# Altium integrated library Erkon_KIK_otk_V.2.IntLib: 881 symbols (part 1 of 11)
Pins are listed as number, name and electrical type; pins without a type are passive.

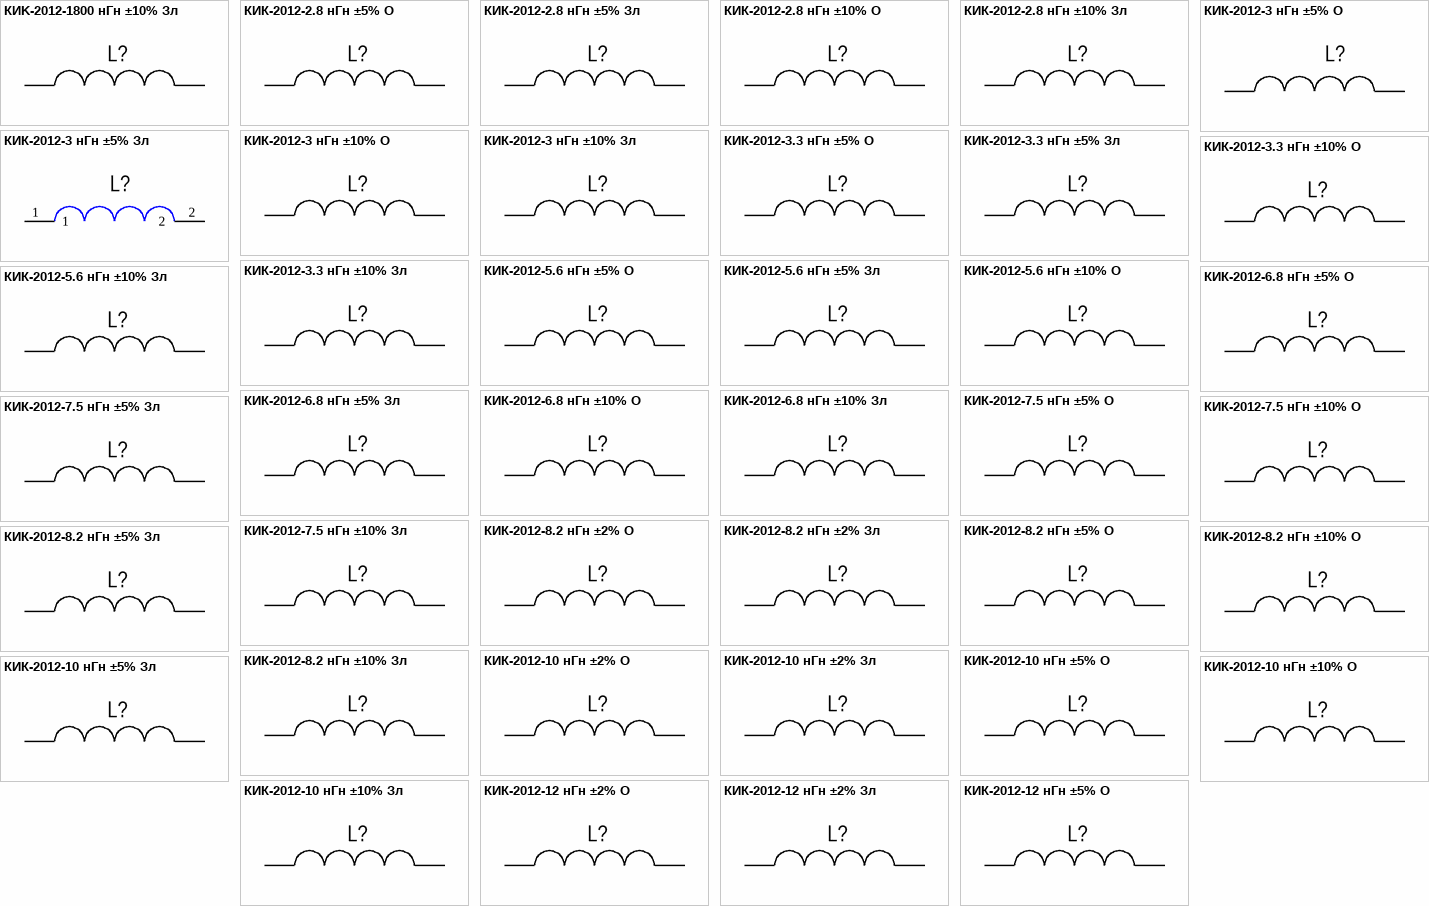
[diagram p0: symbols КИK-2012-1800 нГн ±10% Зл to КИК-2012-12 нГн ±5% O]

## КИK-2012-1800 нГн ±10% Зл
designator L?, comment 1800 нГн ±10%  (value not drawn)
Катушка индуктивности с керамическим сердечником и золотым покрытием контактных площадок; Добротность, не менее: 17; Резонансная частота, не менее: 0.120 ГГц; Сопротивление обмотки постоянноми току, не более: 3 Ом; Допустимый ток обмотки: 120 мА; Диапазон рабочих температур: от -60 до +125 ℃; Упаковка: Катушка и лента; Типоразмер: 2012 (0805); Технология монтажа: SMT; Изготовитель: АО "НПО "ЭРКОН"
footprint КИК-2012-Зл (Катушка индуктивности с керамическим сердечникомтипоразмер 2012(0805))
pins: 1, 2

## КИК-2012-2.8 нГн ±5% O
designator L?, comment 2.8 нГн ±5%  (value not drawn)
Катушка индуктивности с керамическим сердечником и  финишным покрытием контактных площадок оловом; Номиналиная индуктивность: 2.8 нГн; Добротность, не менее: 30; Резонансная частота, не менее: 12.20 ГГц; Сопротивление обмотки постоянноми току, не более: 0.06 Ом; Допустимый ток обмотки: 800 мА; Диапазон рабочих температур: от -60 до +125 ℃; Упаковка: Катушка и лента; Технология монтажа: SMT; Изготовитель: АО "НПО "ЭРКОН"; Типоразмер: 2012 (0805)
footprint КИК-2012-O (Катушка индуктивности с керамическим сердечником типоразмер 2012(0805))
pins: 1, 2

## КИК-2012-2.8 нГн ±5% Зл
designator L?, comment 2.8 нГн ±5%  (value not drawn)
Катушка индуктивности с керамическим сердечником и золотым покрытием контактных площадок; Номиналиная индуктивность: 2.8 нГн; Добротность, не менее: 30; Резонансная частота, не менее: 12.20 ГГц; Сопротивление обмотки постоянноми току, не более: 0.06 Ом; Допустимый ток обмотки: 800 мА; Диапазон рабочих температур: от -60 до +125 ℃; Упаковка: Катушка и лента; Типоразмер: 2012 (0805); Технология монтажа: SMT; Изготовитель: АО "НПО "ЭРКОН"
footprint КИК-2012-Зл (Катушка индуктивности с керамическим сердечникомтипоразмер 2012(0805))
pins: 1, 2

## КИК-2012-2.8 нГн ±10% O
designator L?, comment 2.8 нГн ±10%  (value not drawn)
Катушка индуктивности с керамическим сердечником и  финишным покрытием контактных площадок оловом; Номиналиная индуктивность: 2.8 нГн; Добротность, не менее: 30; Резонансная частота, не менее: 12.20 ГГц; Сопротивление обмотки постоянноми току, не более: 0.06 Ом; Допустимый ток обмотки: 800 мА; Диапазон рабочих температур: от -60 до +125 ℃; Упаковка: Катушка и лента; Типоразмер: 2012 (0805); Технология монтажа: SMT; Изготовитель: АО "НПО "ЭРКОН"
footprint КИК-2012-O (Катушка индуктивности с керамическим сердечником типоразмер 2012(0805))
pins: 1, 2

## КИК-2012-2.8 нГн ±10% Зл
designator L?, comment 2.8 нГн ±10%  (value not drawn)
Катушка индуктивности с керамическим сердечником и золотым покрытием контактных площадок; Номиналиная индуктивность: 2.8 нГн; Добротность, не менее: 30; Резонансная частота, не менее: 12.20 ГГц; Сопротивление обмотки постоянноми току, не более: 0.06 Ом; Допустимый ток обмотки: 800 мА; Диапазон рабочих температур: от -60 до +125 ℃; Упаковка: Катушка и лента; Типоразмер: 2012 (0805); Технология монтажа: SMT; Изготовитель: АО "НПО "ЭРКОН"
footprint КИК-2012-Зл (Катушка индуктивности с керамическим сердечникомтипоразмер 2012(0805))
pins: 1, 2

## КИК-2012-3 нГн ±5% O
designator L?, comment 3 нГн ±5%  (value not drawn)
Катушка индуктивности с керамическим сердечником и  финишным покрытием контактных площадок оловом; Номиналиная индуктивность: 3 нГн; Добротность, не менее: 30; Резонансная частота, не менее: 12.20 ГГц; Сопротивление обмотки постоянноми току, не более: 0.06 Ом; Допустимый ток обмотки: 800 мА; Диапазон рабочих температур: от -60 до +125 ℃; Упаковка: Катушка и лента; Типоразмер: 2012 (0805); Технология монтажа: SMT; Изготовитель: АО "НПО "ЭРКОН"
footprint КИК-2012-O (Катушка индуктивности с керамическим сердечником типоразмер 2012(0805))
pins: 1, 2

## КИК-2012-3 нГн ±5% Зл
designator L?, comment 3 нГн ±5%  (value not drawn)
Катушка индуктивности с керамическим сердечником и золотым покрытием контактных площадок; Номиналиная индуктивность: 3 нГн; Добротность, не менее: 30; Резонансная частота, не менее: 12.20 ГГц; Сопротивление обмотки постоянноми току, не более: 0.06 Ом; Допустимый ток обмотки: 800 мА; Диапазон рабочих температур: от -60 до +125 ℃; Упаковка: Катушка и лента; Типоразмер: 2012 (0805); Технология монтажа: SMT; Изготовитель: АО "НПО "ЭРКОН"
footprint КИК-2012-Зл (Катушка индуктивности с керамическим сердечникомтипоразмер 2012(0805))
pins: 1, 2

## КИК-2012-3 нГн ±10% O
designator L?, comment 3 нГн ±10%  (value not drawn)
Катушка индуктивности с керамическим сердечником и  финишным покрытием контактных площадок оловом; Номиналиная индуктивность: 3 нГн; Добротность, не менее: 30; Резонансная частота, не менее: 12.20 ГГц; Сопротивление обмотки постоянноми току, не более: 0.06 Ом; Допустимый ток обмотки: 800 мА; Диапазон рабочих температур: от -60 до +125 ℃; Упаковка: Катушка и лента; Типоразмер: 2012 (0805); Технология монтажа: SMT; Изготовитель: АО "НПО "ЭРКОН"
footprint КИК-2012-O (Катушка индуктивности с керамическим сердечником типоразмер 2012(0805))
pins: 1, 2

## КИК-2012-3 нГн ±10% Зл
designator L?, comment 3 нГн ±10%  (value not drawn)
Катушка индуктивности с керамическим сердечником и золотым покрытием контактных площадок; Номиналиная индуктивность: 3 нГн; Добротность, не менее: 30; Резонансная частота, не менее: 12.20 ГГц; Сопротивление обмотки постоянноми току, не более: 0.06 Ом; Допустимый ток обмотки: 800 мА; Диапазон рабочих температур: от -60 до +125 ℃; Упаковка: Катушка и лента; Типоразмер: 2012 (0805); Технология монтажа: SMT; Изготовитель: АО "НПО "ЭРКОН"
footprint КИК-2012-Зл (Катушка индуктивности с керамическим сердечникомтипоразмер 2012(0805))
pins: 1, 2

## КИК-2012-3.3 нГн ±5% O
designator L?, comment 3.3 нГн ±5%  (value not drawn)
Катушка индуктивности с керамическим сердечником и  финишным покрытием контактных площадок оловом; Номиналиная индуктивность: 3.3 нГн; Добротность, не менее: 30; Резонансная частота, не менее: 12.20 ГГц; Сопротивление обмотки постоянноми току, не более: 0.08 Ом; Допустимый ток обмотки: 600 мА; Диапазон рабочих температур: от -60 до +125 ℃; Упаковка: Катушка и лента; Типоразмер: 2012 (0805); Технология монтажа: SMT; Изготовитель: АО "НПО "ЭРКОН"
footprint КИК-2012-O (Катушка индуктивности с керамическим сердечником типоразмер 2012(0805))
pins: 1, 2

## КИК-2012-3.3 нГн ±5% Зл
designator L?, comment 3.3 нГн ±5%  (value not drawn)
Катушка индуктивности с керамическим сердечником и золотым покрытием контактных площадок; Номиналиная индуктивность: 3.3 нГн; Добротность, не менее: 30; Резонансная частота, не менее: 12.20 ГГц; Сопротивление обмотки постоянноми току, не более: 0.08 Ом; Допустимый ток обмотки: 600 мА; Диапазон рабочих температур: от -60 до +125 ℃; Упаковка: Катушка и лента; Типоразмер: 2012 (0805); Технология монтажа: SMT; Изготовитель: АО "НПО "ЭРКОН"
footprint КИК-2012-Зл (Катушка индуктивности с керамическим сердечникомтипоразмер 2012(0805))
pins: 1, 2

## КИК-2012-3.3 нГн ±10% O
designator L?, comment 3.3 нГн ±10%  (value not drawn)
Катушка индуктивности с керамическим сердечником и  финишным покрытием контактных площадок оловом; Номиналиная индуктивность: 3.3 нГн; Добротность, не менее: 30; Резонансная частота, не менее: 12.20 ГГц; Сопротивление обмотки постоянноми току, не более: 0.08 Ом; Допустимый ток обмотки: 600 мА; Диапазон рабочих температур: от -60 до +125 ℃; Упаковка: Катушка и лента; Типоразмер: 2012 (0805); Технология монтажа: SMT; Изготовитель: АО "НПО "ЭРКОН"
footprint КИК-2012-O (Катушка индуктивности с керамическим сердечником типоразмер 2012(0805))
pins: 1, 2

## КИК-2012-3.3 нГн ±10% Зл
designator L?, comment 3.3 нГн ±10%  (value not drawn)
Катушка индуктивности с керамическим сердечником и золотым покрытием контактных площадок; Номиналиная индуктивность: 3.3 нГн; Добротность, не менее: 30; Резонансная частота, не менее: 12.20 ГГц; Сопротивление обмотки постоянноми току, не более: 0.08 Ом; Допустимый ток обмотки: 600 мА; Диапазон рабочих температур: от -60 до +125 ℃; Упаковка: Катушка и лента; Типоразмер: 2012 (0805); Технология монтажа: SMT; Изготовитель: АО "НПО "ЭРКОН"
footprint КИК-2012-Зл (Катушка индуктивности с керамическим сердечникомтипоразмер 2012(0805))
pins: 1, 2

## КИК-2012-5.6 нГн ±5% O
designator L?, comment 5.6 нГн ±5%  (value not drawn)
Катушка индуктивности с керамическим сердечником и  финишным покрытием контактных площадок оловом; Номиналиная индуктивность: 5.6 нГн; Добротность, не менее: 50; Резонансная частота, не менее: 5.90 ГГц; Сопротивление обмотки постоянноми току, не более: 0.08 Ом; Допустимый ток обмотки: 600 мА; Диапазон рабочих температур: от -60 до +125 ℃; Упаковка: Катушка и лента; Типоразмер: 2012 (0805); Технология монтажа: SMT; Изготовитель: АО "НПО "ЭРКОН"
footprint КИК-2012-O (Катушка индуктивности с керамическим сердечником типоразмер 2012(0805))
pins: 1, 2

## КИК-2012-5.6 нГн ±5% Зл
designator L?, comment 5.6 нГн ±5%  (value not drawn)
Катушка индуктивности с керамическим сердечником и золотым покрытием контактных площадок; Номиналиная индуктивность: 5.6 нГн; Добротность, не менее: 50; Резонансная частота, не менее: 5.90 ГГц; Сопротивление обмотки постоянноми току, не более: 0.08 Ом; Допустимый ток обмотки: 600 мА; Диапазон рабочих температур: от -60 до +125 ℃; Упаковка: Катушка и лента; Типоразмер: 2012 (0805); Технология монтажа: SMT; Изготовитель: АО "НПО "ЭРКОН"
footprint КИК-2012-Зл (Катушка индуктивности с керамическим сердечникомтипоразмер 2012(0805))
pins: 1, 2

## КИК-2012-5.6 нГн ±10% O
designator L?, comment 5.6 нГн ±10%  (value not drawn)
Катушка индуктивности с керамическим сердечником и  финишным покрытием контактных площадок оловом; Номиналиная индуктивность: 5.6 нГн; Добротность, не менее: 50; Резонансная частота, не менее: 5.90 ГГц; Сопротивление обмотки постоянноми току, не более: 0.08 Ом; Допустимый ток обмотки: 600 мА; Диапазон рабочих температур: от -60 до +125 ℃; Упаковка: Катушка и лента; Типоразмер: 2012 (0805); Технология монтажа: SMT; Изготовитель: АО "НПО "ЭРКОН"
footprint КИК-2012-O (Катушка индуктивности с керамическим сердечником типоразмер 2012(0805))
pins: 1, 2

## КИК-2012-5.6 нГн ±10% Зл
designator L?, comment 5.6 нГн ±10%  (value not drawn)
Катушка индуктивности с керамическим сердечником и золотым покрытием контактных площадок; Номиналиная индуктивность: 5.6 нГн; Добротность, не менее: 50; Резонансная частота, не менее: 5.90 ГГц; Сопротивление обмотки постоянноми току, не более: 0.08 Ом; Допустимый ток обмотки: 600 мА; Диапазон рабочих температур: от -60 до +125 ℃; Упаковка: Катушка и лента; Типоразмер: 2012 (0805); Технология монтажа: SMT; Изготовитель: АО "НПО "ЭРКОН"
footprint КИК-2012-Зл (Катушка индуктивности с керамическим сердечникомтипоразмер 2012(0805))
pins: 1, 2

## КИК-2012-6.8 нГн ±5% O
designator L?, comment 6.8 нГн ±5%  (value not drawn)
Катушка индуктивности с керамическим сердечником и  финишным покрытием контактных площадок оловом; Номиналиная индуктивность: 6.8 нГн; Добротность, не менее: 50; Резонансная частота, не менее: 5.60 ГГц; Сопротивление обмотки постоянноми току, не более: 0.11 Ом; Допустимый ток обмотки: 600 мА; Диапазон рабочих температур: от -60 до +125 ℃; Упаковка: Катушка и лента; Типоразмер: 2012 (0805); Технология монтажа: SMT; Изготовитель: АО "НПО "ЭРКОН"
footprint КИК-2012-O (Катушка индуктивности с керамическим сердечником типоразмер 2012(0805))
pins: 1, 2

## КИК-2012-6.8 нГн ±5% Зл
designator L?, comment 6.8 нГн ±5%  (value not drawn)
Катушка индуктивности с керамическим сердечником и золотым покрытием контактных площадок; Номиналиная индуктивность: 6.8 нГн; Добротность, не менее: 50; Резонансная частота, не менее: 5.60 ГГц; Сопротивление обмотки постоянноми току, не более: 0.11 Ом; Допустимый ток обмотки: 600 мА; Диапазон рабочих температур: от -60 до +125 ℃; Упаковка: Катушка и лента; Типоразмер: 2012 (0805); Технология монтажа: SMT; Изготовитель: АО "НПО "ЭРКОН"
footprint КИК-2012-Зл (Катушка индуктивности с керамическим сердечникомтипоразмер 2012(0805))
pins: 1, 2

## КИК-2012-6.8 нГн ±10% O
designator L?, comment 6.8 нГн ±10%  (value not drawn)
Катушка индуктивности с керамическим сердечником и  финишным покрытием контактных площадок оловом; Номиналиная индуктивность: 6.8 нГн; Добротность, не менее: 50; Резонансная частота, не менее: 5.60 ГГц; Сопротивление обмотки постоянноми току, не более: 0.11 Ом; Допустимый ток обмотки: 600 мА; Диапазон рабочих температур: от -60 до +125 ℃; Упаковка: Катушка и лента; Типоразмер: 2012 (0805); Технология монтажа: SMT; Изготовитель: АО "НПО "ЭРКОН"
footprint КИК-2012-O (Катушка индуктивности с керамическим сердечником типоразмер 2012(0805))
pins: 1, 2

## КИК-2012-6.8 нГн ±10% Зл
designator L?, comment 6.8 нГн ±10%  (value not drawn)
Катушка индуктивности с керамическим сердечником и золотым покрытием контактных площадок; Номиналиная индуктивность: 6.8 нГн; Добротность, не менее: 50; Резонансная частота, не менее: 5.60 ГГц; Сопротивление обмотки постоянноми току, не более: 0.11 Ом; Допустимый ток обмотки: 600 мА; Диапазон рабочих температур: от -60 до +125 ℃; Упаковка: Катушка и лента; Типоразмер: 2012 (0805); Технология монтажа: SMT; Изготовитель: АО "НПО "ЭРКОН"
footprint КИК-2012-Зл (Катушка индуктивности с керамическим сердечникомтипоразмер 2012(0805))
pins: 1, 2

## КИК-2012-7.5 нГн ±5% O
designator L?, comment 7.5 нГн ±5%  (value not drawn)
Катушка индуктивности с керамическим сердечником и  финишным покрытием контактных площадок оловом; Номиналиная индуктивность: 7.5 нГн; Добротность, не менее: 50; Резонансная частота, не менее: 4.80 ГГц; Сопротивление обмотки постоянноми току, не более: 0.14 Ом; Допустимый ток обмотки: 600 мА; Диапазон рабочих температур: от -60 до +125 ℃; Упаковка: Катушка и лента; Типоразмер: 2012 (0805); Технология монтажа: SMT; Изготовитель: АО "НПО "ЭРКОН"
footprint КИК-2012-O (Катушка индуктивности с керамическим сердечником типоразмер 2012(0805))
pins: 1, 2

## КИК-2012-7.5 нГн ±5% Зл
designator L?, comment 7.5 нГн ±5%  (value not drawn)
Катушка индуктивности с керамическим сердечником и золотым покрытием контактных площадок; Номиналиная индуктивность: 7.5 нГн; Добротность, не менее: 50; Резонансная частота, не менее: 4.80 ГГц; Сопротивление обмотки постоянноми току, не более: 0.14 Ом; Допустимый ток обмотки: 600 мА; Диапазон рабочих температур: от -60 до +125 ℃; Упаковка: Катушка и лента; Типоразмер: 2012 (0805); Технология монтажа: SMT; Изготовитель: АО "НПО "ЭРКОН"
footprint КИК-2012-Зл (Катушка индуктивности с керамическим сердечникомтипоразмер 2012(0805))
pins: 1, 2

## КИК-2012-7.5 нГн ±10% O
designator L?, comment 7.5 нГн ±10%  (value not drawn)
Катушка индуктивности с керамическим сердечником и  финишным покрытием контактных площадок оловом; Номиналиная индуктивность: 7.5 нГн; Добротность, не менее: 50; Резонансная частота, не менее: 4.80 ГГц; Сопротивление обмотки постоянноми току, не более: 0.14 Ом; Допустимый ток обмотки: 600 мА; Диапазон рабочих температур: от -60 до +125 ℃; Упаковка: Катушка и лента; Типоразмер: 2012 (0805); Технология монтажа: SMT; Изготовитель: АО "НПО "ЭРКОН"
footprint КИК-2012-O (Катушка индуктивности с керамическим сердечником типоразмер 2012(0805))
pins: 1, 2

## КИК-2012-7.5 нГн ±10% Зл
designator L?, comment 7.5 нГн ±10%  (value not drawn)
Катушка индуктивности с керамическим сердечником и золотым покрытием контактных площадок; Номиналиная индуктивность: 7.5 нГн; Добротность, не менее: 50; Резонансная частота, не менее: 4.80 ГГц; Сопротивление обмотки постоянноми току, не более: 0.14 Ом; Допустимый ток обмотки: 600 мА; Диапазон рабочих температур: от -60 до +125 ℃; Упаковка: Катушка и лента; Типоразмер: 2012 (0805); Технология монтажа: SMT; Изготовитель: АО "НПО "ЭРКОН"
footprint КИК-2012-Зл (Катушка индуктивности с керамическим сердечникомтипоразмер 2012(0805))
pins: 1, 2

## КИК-2012-8.2 нГн ±2% O
designator L?, comment 8.2 нГн ±2%  (value not drawn)
Катушка индуктивности с керамическим сердечником и  финишным покрытием контактных площадок оловом; Номиналиная индуктивность: 8.2 нГн; Добротность, не менее: 50; Резонансная частота, не менее: 4.40 ГГц; Сопротивление обмотки постоянноми току, не более: 0.12 Ом; Допустимый ток обмотки: 600 мА; Диапазон рабочих температур: от -60 до +125 ℃; Упаковка: Катушка и лента; Типоразмер: 2012 (0805); Технология монтажа: SMT; Изготовитель: АО "НПО "ЭРКОН"
footprint КИК-2012-O (Катушка индуктивности с керамическим сердечником типоразмер 2012(0805))
pins: 1, 2

## КИК-2012-8.2 нГн ±2% Зл
designator L?, comment 8.2 нГн ±2%  (value not drawn)
Катушка индуктивности с керамическим сердечником и золотым покрытием контактных площадок; Номиналиная индуктивность: 8.2 нГн; Добротность, не менее: 50; Резонансная частота, не менее: 4.40 ГГц; Сопротивление обмотки постоянноми току, не более: 0.12 Ом; Допустимый ток обмотки: 600 мА; Диапазон рабочих температур: от -60 до +125 ℃; Упаковка: Катушка и лента; Типоразмер: 2012 (0805); Технология монтажа: SMT; Изготовитель: АО "НПО "ЭРКОН"
footprint КИК-2012-Зл (Катушка индуктивности с керамическим сердечникомтипоразмер 2012(0805))
pins: 1, 2

## КИК-2012-8.2 нГн ±5% O
designator L?, comment 8.2 нГн ±5%  (value not drawn)
Катушка индуктивности с керамическим сердечником и  финишным покрытием контактных площадок оловом; Номиналиная индуктивность: 8.2 нГн; Добротность, не менее: 50; Резонансная частота, не менее: 4.40 ГГц; Сопротивление обмотки постоянноми току, не более: 0.12 Ом; Допустимый ток обмотки: 600 мА; Диапазон рабочих температур: от -60 до +125 ℃; Упаковка: Катушка и лента; Типоразмер: 2012 (0805); Технология монтажа: SMT; Изготовитель: АО "НПО "ЭРКОН"
footprint КИК-2012-O (Катушка индуктивности с керамическим сердечником типоразмер 2012(0805))
pins: 1, 2

## КИК-2012-8.2 нГн ±5% Зл
designator L?, comment 8.2 нГн ±5%  (value not drawn)
Катушка индуктивности с керамическим сердечником и золотым покрытием контактных площадок; Номиналиная индуктивность: 8.2 нГн; Добротность, не менее: 50; Резонансная частота, не менее: 4.40 ГГц; Сопротивление обмотки постоянноми току, не более: 0.12 Ом; Допустимый ток обмотки: 600 мА; Диапазон рабочих температур: от -60 до +125 ℃; Упаковка: Катушка и лента; Типоразмер: 2012 (0805); Технология монтажа: SMT; Изготовитель: АО "НПО "ЭРКОН"
footprint КИК-2012-Зл (Катушка индуктивности с керамическим сердечникомтипоразмер 2012(0805))
pins: 1, 2

## КИК-2012-8.2 нГн ±10% O
designator L?, comment 8.2 нГн ±10%  (value not drawn)
Катушка индуктивности с керамическим сердечником и  финишным покрытием контактных площадок оловом; Номиналиная индуктивность: 8.2 нГн; Добротность, не менее: 50; Резонансная частота, не менее: 4.40 ГГц; Сопротивление обмотки постоянноми току, не более: 0.12 Ом; Допустимый ток обмотки: 600 мА; Диапазон рабочих температур: от -60 до +125 ℃; Упаковка: Катушка и лента; Типоразмер: 2012 (0805); Технология монтажа: SMT; Изготовитель: АО "НПО "ЭРКОН"
footprint КИК-2012-O (Катушка индуктивности с керамическим сердечником типоразмер 2012(0805))
pins: 1, 2

## КИК-2012-8.2 нГн ±10% Зл
designator L?, comment 8.2 нГн ±10%  (value not drawn)
Катушка индуктивности с керамическим сердечником и золотым покрытием контактных площадок; Номиналиная индуктивность: 8.2 нГн; Добротность, не менее: 50; Резонансная частота, не менее: 4.40 ГГц; Сопротивление обмотки постоянноми току, не более: 0.12 Ом; Допустимый ток обмотки: 600 мА; Диапазон рабочих температур: от -60 до +125 ℃; Упаковка: Катушка и лента; Типоразмер: 2012 (0805); Технология монтажа: SMT; Изготовитель: АО "НПО "ЭРКОН"
footprint КИК-2012-Зл (Катушка индуктивности с керамическим сердечникомтипоразмер 2012(0805))
pins: 1, 2

## КИК-2012-10 нГн ±2% O
designator L?, comment 10 нГн ±2%  (value not drawn)
Катушка индуктивности с керамическим сердечником и  финишным покрытием контактных площадок оловом; Номиналиная индуктивность: 10 нГн; Добротность, не менее: 50; Резонансная частота, не менее: 4.30 ГГц; Сопротивление обмотки постоянноми току, не более: 0.10 Ом; Допустимый ток обмотки: 600 мА; Диапазон рабочих температур: от -60 до +125 ℃; Упаковка: Катушка и лента; Типоразмер: 2012 (0805); Технология монтажа: SMT; Изготовитель: АО "НПО "ЭРКОН"
footprint КИК-2012-O (Катушка индуктивности с керамическим сердечником типоразмер 2012(0805))
pins: 1, 2

## КИК-2012-10 нГн ±2% Зл
designator L?, comment 10 нГн ±2%  (value not drawn)
Катушка индуктивности с керамическим сердечником и золотым покрытием контактных площадок; Номиналиная индуктивность: 10 нГн; Добротность, не менее: 50; Резонансная частота, не менее: 4.30 ГГц; Сопротивление обмотки постоянноми току, не более: 0.10 Ом; Допустимый ток обмотки: 600 мА; Диапазон рабочих температур: от -60 до +125 ℃; Упаковка: Катушка и лента; Типоразмер: 2012 (0805); Технология монтажа: SMT; Изготовитель: АО "НПО "ЭРКОН"
footprint КИК-2012-Зл (Катушка индуктивности с керамическим сердечникомтипоразмер 2012(0805))
pins: 1, 2

## КИК-2012-10 нГн ±5% O
designator L?, comment 10 нГн ±5%  (value not drawn)
Катушка индуктивности с керамическим сердечником и  финишным покрытием контактных площадок оловом; Номиналиная индуктивность: 10 нГн; Добротность, не менее: 50; Резонансная частота, не менее: 4.30 ГГц; Сопротивление обмотки постоянноми току, не более: 0.10 Ом; Допустимый ток обмотки: 600 мА; Диапазон рабочих температур: от -60 до +125 ℃; Упаковка: Катушка и лента; Типоразмер: 2012 (0805); Технология монтажа: SMT; Изготовитель: АО "НПО "ЭРКОН"
footprint КИК-2012-O (Катушка индуктивности с керамическим сердечником типоразмер 2012(0805))
pins: 1, 2

## КИК-2012-10 нГн ±5% Зл
designator L?, comment 10 нГн ±5%  (value not drawn)
Катушка индуктивности с керамическим сердечником и золотым покрытием контактных площадок; Номиналиная индуктивность: 10 нГн; Добротность, не менее: 50; Резонансная частота, не менее: 4.30 ГГц; Сопротивление обмотки постоянноми току, не более: 0.10 Ом; Допустимый ток обмотки: 600 мА; Диапазон рабочих температур: от -60 до +125 ℃; Упаковка: Катушка и лента; Типоразмер: 2012 (0805); Технология монтажа: SMT; Изготовитель: АО "НПО "ЭРКОН"
footprint КИК-2012-Зл (Катушка индуктивности с керамическим сердечникомтипоразмер 2012(0805))
pins: 1, 2

## КИК-2012-10 нГн ±10% O
designator L?, comment 10 нГн ±10%  (value not drawn)
Катушка индуктивности с керамическим сердечником и  финишным покрытием контактных площадок оловом; Номиналиная индуктивность: 10 нГн; Добротность, не менее: 50; Резонансная частота, не менее: 4.30 ГГц; Сопротивление обмотки постоянноми току, не более: 0.10 Ом; Допустимый ток обмотки: 600 мА; Диапазон рабочих температур: от -60 до +125 ℃; Упаковка: Катушка и лента; Типоразмер: 2012 (0805); Технология монтажа: SMT; Изготовитель: АО "НПО "ЭРКОН"
footprint КИК-2012-O (Катушка индуктивности с керамическим сердечником типоразмер 2012(0805))
pins: 1, 2

## КИК-2012-10 нГн ±10% Зл
designator L?, comment 10 нГн ±10%  (value not drawn)
Катушка индуктивности с керамическим сердечником и золотым покрытием контактных площадок; Номиналиная индуктивность: 10 нГн; Добротность, не менее: 50; Резонансная частота, не менее: 4.30 ГГц; Сопротивление обмотки постоянноми току, не более: 0.10 Ом; Допустимый ток обмотки: 600 мА; Диапазон рабочих температур: от -60 до +125 ℃; Упаковка: Катушка и лента; Типоразмер: 2012 (0805); Технология монтажа: SMT; Изготовитель: АО "НПО "ЭРКОН"
footprint КИК-2012-Зл (Катушка индуктивности с керамическим сердечникомтипоразмер 2012(0805))
pins: 1, 2

## КИК-2012-12 нГн ±2% O
designator L?, comment 12 нГн ±2%  (value not drawn)
Катушка индуктивности с керамическим сердечником и  финишным покрытием контактных площадок оловом; Номиналиная индуктивность: 12 нГн; Добротность, не менее: 50; Резонансная частота, не менее: 4.00 ГГц; Сопротивление обмотки постоянноми току, не более: 0.15 Ом; Допустимый ток обмотки: 600 мА; Диапазон рабочих температур: от -60 до +125 ℃; Упаковка: Катушка и лента; Типоразмер: 2012 (0805); Технология монтажа: SMT; Изготовитель: АО "НПО "ЭРКОН"
footprint КИК-2012-O (Катушка индуктивности с керамическим сердечником типоразмер 2012(0805))
pins: 1, 2

## КИК-2012-12 нГн ±2% Зл
designator L?, comment 12 нГн ±2%  (value not drawn)
Катушка индуктивности с керамическим сердечником и золотым покрытием контактных площадок; Номиналиная индуктивность: 12 нГн; Добротность, не менее: 50; Резонансная частота, не менее: 4.00 ГГц; Сопротивление обмотки постоянноми току, не более: 0.15 Ом; Допустимый ток обмотки: 600 мА; Диапазон рабочих температур: от -60 до +125 ℃; Упаковка: Катушка и лента; Типоразмер: 2012 (0805); Технология монтажа: SMT; Изготовитель: АО "НПО "ЭРКОН"
footprint КИК-2012-Зл (Катушка индуктивности с керамическим сердечникомтипоразмер 2012(0805))
pins: 1, 2

## КИК-2012-12 нГн ±5% O
designator L?, comment 12 нГн ±5%  (value not drawn)
Катушка индуктивности с керамическим сердечником и  финишным покрытием контактных площадок оловом; Номиналиная индуктивность: 12 нГн; Добротность, не менее: 50; Резонансная частота, не менее: 4.00 ГГц; Сопротивление обмотки постоянноми току, не более: 0.15 Ом; Допустимый ток обмотки: 600 мА; Диапазон рабочих температур: от -60 до +125 ℃; Упаковка: Катушка и лента; Типоразмер: 2012 (0805); Технология монтажа: SMT; Изготовитель: АО "НПО "ЭРКОН"
footprint КИК-2012-O (Катушка индуктивности с керамическим сердечником типоразмер 2012(0805))
pins: 1, 2

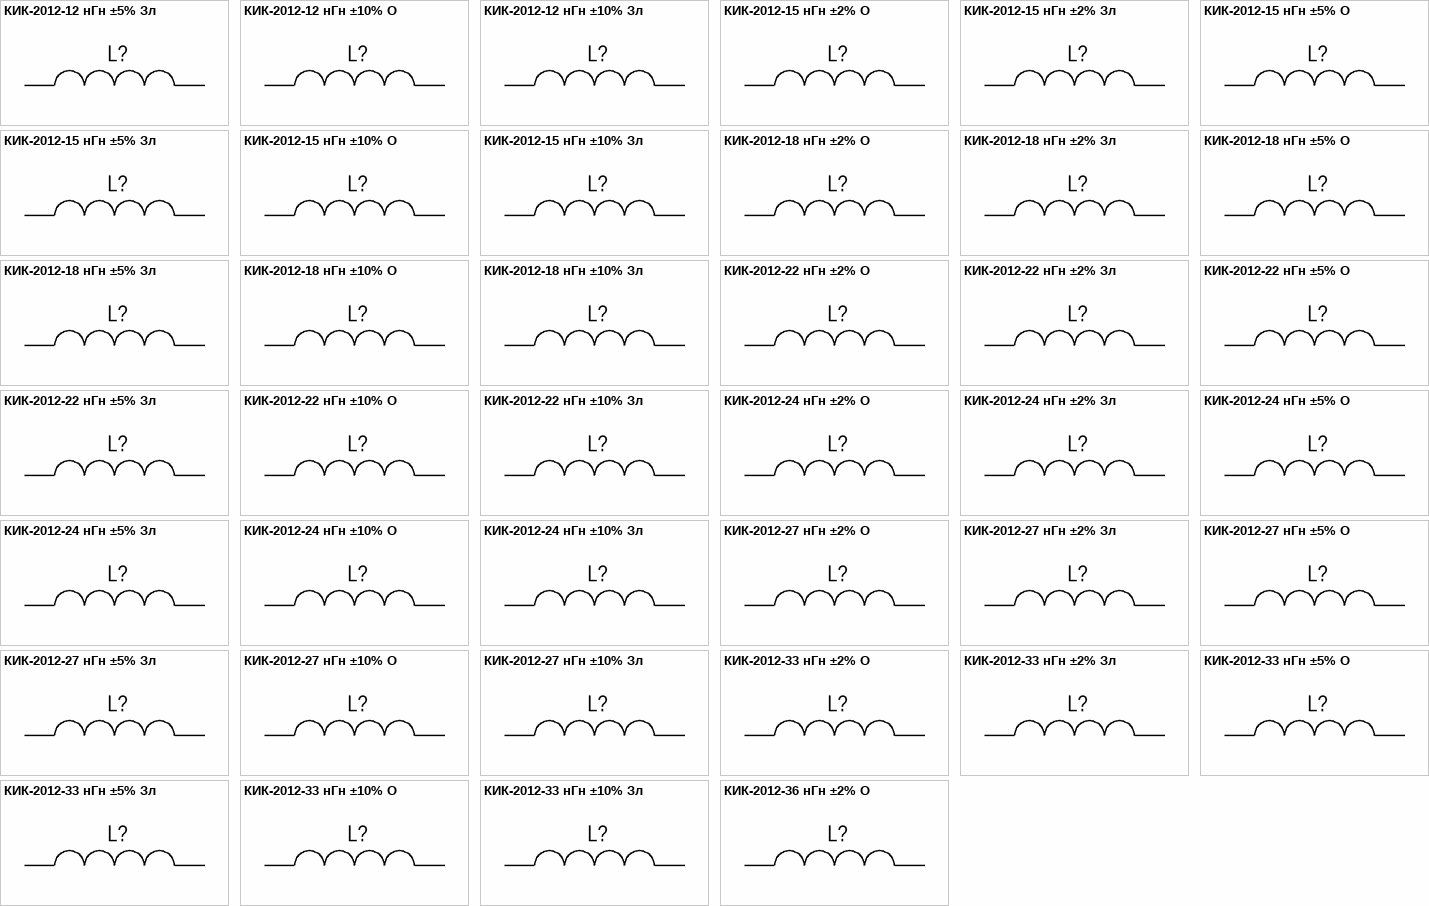
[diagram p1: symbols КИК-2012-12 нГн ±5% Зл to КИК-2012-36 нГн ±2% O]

## КИК-2012-12 нГн ±5% Зл
designator L?, comment 12 нГн ±5%  (value not drawn)
Катушка индуктивности с керамическим сердечником и золотым покрытием контактных площадок; Номиналиная индуктивность: 12 нГн; Добротность, не менее: 50; Резонансная частота, не менее: 4.00 ГГц; Сопротивление обмотки постоянноми току, не более: 0.15 Ом; Допустимый ток обмотки: 600 мА; Диапазон рабочих температур: от -60 до +125 ℃; Упаковка: Катушка и лента; Типоразмер: 2012 (0805); Технология монтажа: SMT; Изготовитель: АО "НПО "ЭРКОН"
footprint КИК-2012-Зл (Катушка индуктивности с керамическим сердечникомтипоразмер 2012(0805))
pins: 1, 2

## КИК-2012-12 нГн ±10% O
designator L?, comment 12 нГн ±10%  (value not drawn)
Катушка индуктивности с керамическим сердечником и  финишным покрытием контактных площадок оловом; Номиналиная индуктивность: 12 нГн; Добротность, не менее: 50; Резонансная частота, не менее: 4.00 ГГц; Сопротивление обмотки постоянноми току, не более: 0.15 Ом; Допустимый ток обмотки: 600 мА; Диапазон рабочих температур: от -60 до +125 ℃; Упаковка: Катушка и лента; Типоразмер: 2012 (0805); Технология монтажа: SMT; Изготовитель: АО "НПО "ЭРКОН"
footprint КИК-2012-O (Катушка индуктивности с керамическим сердечником типоразмер 2012(0805))
pins: 1, 2

## КИК-2012-12 нГн ±10% Зл
designator L?, comment 12 нГн ±10%  (value not drawn)
Катушка индуктивности с керамическим сердечником и золотым покрытием контактных площадок; Номиналиная индуктивность: 12 нГн; Добротность, не менее: 50; Резонансная частота, не менее: 4.00 ГГц; Сопротивление обмотки постоянноми току, не более: 0.15 Ом; Допустимый ток обмотки: 600 мА; Диапазон рабочих температур: от -60 до +125 ℃; Упаковка: Катушка и лента; Типоразмер: 2012 (0805); Технология монтажа: SMT; Изготовитель: АО "НПО "ЭРКОН"
footprint КИК-2012-Зл (Катушка индуктивности с керамическим сердечникомтипоразмер 2012(0805))
pins: 1, 2

## КИК-2012-15 нГн ±2% O
designator L?, comment 15 нГн ±2%  (value not drawn)
Катушка индуктивности с керамическим сердечником и  финишным покрытием контактных площадок оловом; Номиналиная индуктивность: 15 нГн; Добротность, не менее: 50; Резонансная частота, не менее: 3.20 ГГц; Сопротивление обмотки постоянноми току, не более: 0.17 Ом; Допустимый ток обмотки: 600 мА; Диапазон рабочих температур: от -60 до +125 ℃; Упаковка: Катушка и лента; Типоразмер: 2012 (0805); Технология монтажа: SMT; Изготовитель: АО "НПО "ЭРКОН"
footprint КИК-2012-O (Катушка индуктивности с керамическим сердечником типоразмер 2012(0805))
pins: 1, 2

## КИК-2012-15 нГн ±2% Зл
designator L?, comment 15 нГн ±2%  (value not drawn)
Катушка индуктивности с керамическим сердечником и золотым покрытием контактных площадок; Номиналиная индуктивность: 15 нГн; Добротность, не менее: 50; Резонансная частота, не менее: 3.20 ГГц; Сопротивление обмотки постоянноми току, не более: 0.17 Ом; Допустимый ток обмотки: 600 мА; Диапазон рабочих температур: от -60 до +125 ℃; Упаковка: Катушка и лента; Типоразмер: 2012 (0805); Технология монтажа: SMT; Изготовитель: АО "НПО "ЭРКОН"
footprint КИК-2012-Зл (Катушка индуктивности с керамическим сердечникомтипоразмер 2012(0805))
pins: 1, 2

## КИК-2012-15 нГн ±5% O
designator L?, comment 15 нГн ±5%  (value not drawn)
Катушка индуктивности с керамическим сердечником и  финишным покрытием контактных площадок оловом; Номиналиная индуктивность: 15 нГн; Добротность, не менее: 50; Резонансная частота, не менее: 3.20 ГГц; Сопротивление обмотки постоянноми току, не более: 0.17 Ом; Допустимый ток обмотки: 600 мА; Диапазон рабочих температур: от -60 до +125 ℃; Упаковка: Катушка и лента; Типоразмер: 2012 (0805); Технология монтажа: SMT; Изготовитель: АО "НПО "ЭРКОН"
footprint КИК-2012-O (Катушка индуктивности с керамическим сердечником типоразмер 2012(0805))
pins: 1, 2

## КИК-2012-15 нГн ±5% Зл
designator L?, comment 15 нГн ±5%  (value not drawn)
Катушка индуктивности с керамическим сердечником и золотым покрытием контактных площадок; Номиналиная индуктивность: 15 нГн; Добротность, не менее: 50; Резонансная частота, не менее: 3.20 ГГц; Сопротивление обмотки постоянноми току, не более: 0.17 Ом; Допустимый ток обмотки: 600 мА; Диапазон рабочих температур: от -60 до +125 ℃; Упаковка: Катушка и лента; Типоразмер: 2012 (0805); Технология монтажа: SMT; Изготовитель: АО "НПО "ЭРКОН"
footprint КИК-2012-Зл (Катушка индуктивности с керамическим сердечникомтипоразмер 2012(0805))
pins: 1, 2

## КИК-2012-15 нГн ±10% O
designator L?, comment 15 нГн ±10%  (value not drawn)
Катушка индуктивности с керамическим сердечником и  финишным покрытием контактных площадок оловом; Номиналиная индуктивность: 15 нГн; Добротность, не менее: 50; Резонансная частота, не менее: 3.20 ГГц; Сопротивление обмотки постоянноми току, не более: 0.17 Ом; Допустимый ток обмотки: 600 мА; Диапазон рабочих температур: от -60 до +125 ℃; Упаковка: Катушка и лента; Типоразмер: 2012 (0805); Технология монтажа: SMT; Изготовитель: АО "НПО "ЭРКОН"
footprint КИК-2012-O (Катушка индуктивности с керамическим сердечником типоразмер 2012(0805))
pins: 1, 2

## КИК-2012-15 нГн ±10% Зл
designator L?, comment 15 нГн ±10%  (value not drawn)
Катушка индуктивности с керамическим сердечником и  финишным покрытием контактных площадок оловом; Номиналиная индуктивность: 15 нГн; Добротность, не менее: 50; Резонансная частота, не менее: 3.20 ГГц; Сопротивление обмотки постоянноми току, не более: 0.17 Ом; Допустимый ток обмотки: 600 мА; Диапазон рабочих температур: от -60 до +125 ℃; Упаковка: Катушка и лента; Типоразмер: 2012 (0805); Технология монтажа: SMT; Изготовитель: АО "НПО "ЭРКОН"
footprint КИК-2012-O (Катушка индуктивности с керамическим сердечником типоразмер 2012(0805))
pins: 1, 2

## КИК-2012-18 нГн ±2% O
designator L?, comment 18 нГн ±2%  (value not drawn)
Катушка индуктивности с керамическим сердечником и  финишным покрытием контактных площадок оловом; Номиналиная индуктивность: 18 нГн; Добротность, не менее: 50; Резонансная частота, не менее: 3.10 ГГц; Сопротивление обмотки постоянноми току, не более: 0.20 Ом; Допустимый ток обмотки: 600 мА; Диапазон рабочих температур: от -60 до +125 ℃; Упаковка: Катушка и лента; Типоразмер: 2012 (0805); Технология монтажа: SMT; Изготовитель: АО "НПО "ЭРКОН"
footprint КИК-2012-O (Катушка индуктивности с керамическим сердечником типоразмер 2012(0805))
pins: 1, 2

## КИК-2012-18 нГн ±2% Зл
designator L?, comment 18 нГн ±2%  (value not drawn)
Катушка индуктивности с керамическим сердечником и золотым покрытием контактных площадок; Номиналиная индуктивность: 18 нГн; Добротность, не менее: 50; Резонансная частота, не менее: 3.10 ГГц; Сопротивление обмотки постоянноми току, не более: 0.20 Ом; Допустимый ток обмотки: 600 мА; Диапазон рабочих температур: от -60 до +125 ℃; Упаковка: Катушка и лента; Типоразмер: 2012 (0805); Технология монтажа: SMT; Изготовитель: АО "НПО "ЭРКОН"
footprint КИК-2012-Зл (Катушка индуктивности с керамическим сердечникомтипоразмер 2012(0805))
pins: 1, 2

## КИК-2012-18 нГн ±5% O
designator L?, comment 18 нГн ±5%  (value not drawn)
Катушка индуктивности с керамическим сердечником и  финишным покрытием контактных площадок оловом; Номиналиная индуктивность: 18 нГн; Добротность, не менее: 50; Резонансная частота, не менее: 3.10 ГГц; Сопротивление обмотки постоянноми току, не более: 0.20 Ом; Допустимый ток обмотки: 600 мА; Диапазон рабочих температур: от -60 до +125 ℃; Упаковка: Катушка и лента; Типоразмер: 2012 (0805); Технология монтажа: SMT; Изготовитель: АО "НПО "ЭРКОН"
footprint КИК-2012-O (Катушка индуктивности с керамическим сердечником типоразмер 2012(0805))
pins: 1, 2

## КИК-2012-18 нГн ±5% Зл
designator L?, comment 18 нГн ±5%  (value not drawn)
Катушка индуктивности с керамическим сердечником и золотым покрытием контактных площадок; Номиналиная индуктивность: 18 нГн; Добротность, не менее: 50; Резонансная частота, не менее: 3.10 ГГц; Сопротивление обмотки постоянноми току, не более: 0.20 Ом; Допустимый ток обмотки: 600 мА; Диапазон рабочих температур: от -60 до +125 ℃; Упаковка: Катушка и лента; Типоразмер: 2012 (0805); Технология монтажа: SMT; Изготовитель: АО "НПО "ЭРКОН"
footprint КИК-2012-Зл (Катушка индуктивности с керамическим сердечникомтипоразмер 2012(0805))
pins: 1, 2

## КИК-2012-18 нГн ±10% O
designator L?, comment 18 нГн ±10%  (value not drawn)
Катушка индуктивности с керамическим сердечником и  финишным покрытием контактных площадок оловом; Номиналиная индуктивность: 18 нГн; Добротность, не менее: 50; Резонансная частота, не менее: 3.10 ГГц; Сопротивление обмотки постоянноми току, не более: 0.20 Ом; Допустимый ток обмотки: 600 мА; Диапазон рабочих температур: от -60 до +125 ℃; Упаковка: Катушка и лента; Типоразмер: 2012 (0805); Технология монтажа: SMT; Изготовитель: АО "НПО "ЭРКОН"
footprint КИК-2012-O (Катушка индуктивности с керамическим сердечником типоразмер 2012(0805))
pins: 1, 2

## КИК-2012-18 нГн ±10% Зл
designator L?, comment 18 нГн ±10%  (value not drawn)
Катушка индуктивности с керамическим сердечником и золотым покрытием контактных площадок; Номиналиная индуктивность: 18 нГн; Добротность, не менее: 50; Резонансная частота, не менее: 3.10 ГГц; Сопротивление обмотки постоянноми току, не более: 0.20 Ом; Допустимый ток обмотки: 600 мА; Диапазон рабочих температур: от -60 до +125 ℃; Упаковка: Катушка и лента; Типоразмер: 2012 (0805); Технология монтажа: SMT; Изготовитель: АО "НПО "ЭРКОН"
footprint КИК-2012-Зл (Катушка индуктивности с керамическим сердечникомтипоразмер 2012(0805))
pins: 1, 2

## КИК-2012-22 нГн ±2% O
designator L?, comment 22 нГн ±2%  (value not drawn)
Катушка индуктивности с керамическим сердечником и  финишным покрытием контактных площадок оловом; Номиналиная индуктивность: 22 нГн; Добротность, не менее: 50; Резонансная частота, не менее: 2.60 ГГц; Сопротивление обмотки постоянноми току, не более: 0.22 Ом; Допустимый ток обмотки: 500 мА; Диапазон рабочих температур: от -60 до +125 ℃; Упаковка: Катушка и лента; Типоразмер: 2012 (0805); Технология монтажа: SMT; Изготовитель: АО "НПО "ЭРКОН"
footprint КИК-2012-O (Катушка индуктивности с керамическим сердечником типоразмер 2012(0805))
pins: 1, 2

## КИК-2012-22 нГн ±2% Зл
designator L?, comment 22 нГн ±2%  (value not drawn)
Катушка индуктивности с керамическим сердечником и золотым покрытием контактных площадок; Номиналиная индуктивность: 22 нГн; Добротность, не менее: 50; Резонансная частота, не менее: 2.60 ГГц; Сопротивление обмотки постоянноми току, не более: 0.22 Ом; Допустимый ток обмотки: 500 мА; Диапазон рабочих температур: от -60 до +125 ℃; Упаковка: Катушка и лента; Типоразмер: 2012 (0805); Технология монтажа: SMT; Изготовитель: АО "НПО "ЭРКОН"
footprint КИК-2012-Зл (Катушка индуктивности с керамическим сердечникомтипоразмер 2012(0805))
pins: 1, 2

## КИК-2012-22 нГн ±5% O
designator L?, comment 22 нГн ±5%  (value not drawn)
Катушка индуктивности с керамическим сердечником и  финишным покрытием контактных площадок оловом; Номиналиная индуктивность: 22 нГн; Добротность, не менее: 50; Резонансная частота, не менее: 2.60 ГГц; Сопротивление обмотки постоянноми току, не более: 0.22 Ом; Допустимый ток обмотки: 500 мА; Диапазон рабочих температур: от -60 до +125 ℃; Упаковка: Катушка и лента; Типоразмер: 2012 (0805); Технология монтажа: SMT; Изготовитель: АО "НПО "ЭРКОН"
footprint КИК-2012-O (Катушка индуктивности с керамическим сердечником типоразмер 2012(0805))
pins: 1, 2

## КИК-2012-22 нГн ±5% Зл
designator L?, comment 22 нГн ±5%  (value not drawn)
Катушка индуктивности с керамическим сердечником и золотым покрытием контактных площадок; Номиналиная индуктивность: 22 нГн; Добротность, не менее: 50; Резонансная частота, не менее: 2.60 ГГц; Сопротивление обмотки постоянноми току, не более: 0.22 Ом; Допустимый ток обмотки: 500 мА; Диапазон рабочих температур: от -60 до +125 ℃; Упаковка: Катушка и лента; Типоразмер: 2012 (0805); Технология монтажа: SMT; Изготовитель: АО "НПО "ЭРКОН"
footprint КИК-2012-Зл (Катушка индуктивности с керамическим сердечникомтипоразмер 2012(0805))
pins: 1, 2

## КИК-2012-22 нГн ±10% O
designator L?, comment 22 нГн ±10%  (value not drawn)
Катушка индуктивности с керамическим сердечником и  финишным покрытием контактных площадок оловом; Номиналиная индуктивность: 22 нГн; Добротность, не менее: 50; Резонансная частота, не менее: 2.60 ГГц; Сопротивление обмотки постоянноми току, не более: 0.22 Ом; Допустимый ток обмотки: 500 мА; Диапазон рабочих температур: от -60 до +125 ℃; Упаковка: Катушка и лента; Типоразмер: 2012 (0805); Технология монтажа: SMT; Изготовитель: АО "НПО "ЭРКОН"
footprint КИК-2012-O (Катушка индуктивности с керамическим сердечником типоразмер 2012(0805))
pins: 1, 2

## КИК-2012-22 нГн ±10% Зл
designator L?, comment 22 нГн ±10%  (value not drawn)
Катушка индуктивности с керамическим сердечником и золотым покрытием контактных площадок; Номиналиная индуктивность: 22 нГн; Добротность, не менее: 50; Резонансная частота, не менее: 2.60 ГГц; Сопротивление обмотки постоянноми току, не более: 0.22 Ом; Допустимый ток обмотки: 500 мА; Диапазон рабочих температур: от -60 до +125 ℃; Упаковка: Катушка и лента; Типоразмер: 2012 (0805); Технология монтажа: SMT; Изготовитель: АО "НПО "ЭРКОН"
footprint КИК-2012-Зл (Катушка индуктивности с керамическим сердечникомтипоразмер 2012(0805))
pins: 1, 2

## КИК-2012-24 нГн ±2% O
designator L?, comment 24 нГн ±2%  (value not drawn)
Катушка индуктивности с керамическим сердечником и  финишным покрытием контактных площадок оловом; Номиналиная индуктивность: 24 нГн; Добротность, не менее: 50; Резонансная частота, не менее: 2.40 ГГц; Сопротивление обмотки постоянноми току, не более: 0.22 Ом; Допустимый ток обмотки: 500 мА; Диапазон рабочих температур: от -60 до +125 ℃; Упаковка: Катушка и лента; Типоразмер: 2012 (0805); Технология монтажа: SMT; Изготовитель: АО "НПО "ЭРКОН"
footprint КИК-2012-O (Катушка индуктивности с керамическим сердечником типоразмер 2012(0805))
pins: 1, 2

## КИК-2012-24 нГн ±2% Зл
designator L?, comment 24 нГн ±2%  (value not drawn)
Катушка индуктивности с керамическим сердечником и золотым покрытием контактных площадок; Номиналиная индуктивность: 24 нГн; Добротность, не менее: 50; Резонансная частота, не менее: 2.40 ГГц; Сопротивление обмотки постоянноми току, не более: 0.22 Ом; Допустимый ток обмотки: 500 мА; Диапазон рабочих температур: от -60 до +125 ℃; Упаковка: Катушка и лента; Типоразмер: 2012 (0805); Технология монтажа: SMT; Изготовитель: АО "НПО "ЭРКОН"
footprint КИК-2012-Зл (Катушка индуктивности с керамическим сердечникомтипоразмер 2012(0805))
pins: 1, 2

## КИК-2012-24 нГн ±5% O
designator L?, comment 24 нГн ±5%  (value not drawn)
Катушка индуктивности с керамическим сердечником и  финишным покрытием контактных площадок оловом; Номиналиная индуктивность: 24 нГн; Добротность, не менее: 50; Резонансная частота, не менее: 2.40 ГГц; Сопротивление обмотки постоянноми току, не более: 0.22 Ом; Допустимый ток обмотки: 500 мА; Диапазон рабочих температур: от -60 до +125 ℃; Упаковка: Катушка и лента; Типоразмер: 2012 (0805); Технология монтажа: SMT; Изготовитель: АО "НПО "ЭРКОН"
footprint КИК-2012-O (Катушка индуктивности с керамическим сердечником типоразмер 2012(0805))
pins: 1, 2

## КИК-2012-24 нГн ±5% Зл
designator L?, comment 24 нГн ±5%  (value not drawn)
Катушка индуктивности с керамическим сердечником и золотым покрытием контактных площадок; Номиналиная индуктивность: 24 нГн; Добротность, не менее: 50; Резонансная частота, не менее: 2.40 ГГц; Сопротивление обмотки постоянноми току, не более: 0.22 Ом; Допустимый ток обмотки: 500 мА; Диапазон рабочих температур: от -60 до +125 ℃; Упаковка: Катушка и лента; Типоразмер: 2012 (0805); Технология монтажа: SMT; Изготовитель: АО "НПО "ЭРКОН"
footprint КИК-2012-Зл (Катушка индуктивности с керамическим сердечникомтипоразмер 2012(0805))
pins: 1, 2

## КИК-2012-24 нГн ±10% O
designator L?, comment 24 нГн ±10%  (value not drawn)
Катушка индуктивности с керамическим сердечником и  финишным покрытием контактных площадок оловом; Номиналиная индуктивность: 24 нГн; Добротность, не менее: 50; Резонансная частота, не менее: 2.40 ГГц; Сопротивление обмотки постоянноми току, не более: 0.22 Ом; Допустимый ток обмотки: 500 мА; Диапазон рабочих температур: от -60 до +125 ℃; Упаковка: Катушка и лента; Типоразмер: 2012 (0805); Технология монтажа: SMT; Изготовитель: АО "НПО "ЭРКОН"
footprint КИК-2012-O (Катушка индуктивности с керамическим сердечником типоразмер 2012(0805))
pins: 1, 2

## КИК-2012-24 нГн ±10% Зл
designator L?, comment 24 нГн ±10%  (value not drawn)
Катушка индуктивности с керамическим сердечником и золотым покрытием контактных площадок; Номиналиная индуктивность: 24 нГн; Добротность, не менее: 50; Резонансная частота, не менее: 2.40 ГГц; Сопротивление обмотки постоянноми току, не более: 0.22 Ом; Допустимый ток обмотки: 500 мА; Диапазон рабочих температур: от -60 до +125 ℃; Упаковка: Катушка и лента; Типоразмер: 2012 (0805); Технология монтажа: SMT; Изготовитель: АО "НПО "ЭРКОН"
footprint КИК-2012-Зл (Катушка индуктивности с керамическим сердечникомтипоразмер 2012(0805))
pins: 1, 2

## КИК-2012-27 нГн ±2% O
designator L?, comment 27 нГн ±2%  (value not drawn)
Катушка индуктивности с керамическим сердечником и  финишным покрытием контактных площадок оловом; Номиналиная индуктивность: 27 нГн; Добротность, не менее: 50; Резонансная частота, не менее: 2.58 ГГц; Сопротивление обмотки постоянноми току, не более: 0.25 Ом; Допустимый ток обмотки: 500 мА; Диапазон рабочих температур: от -60 до +125 ℃; Упаковка: Катушка и лента; Типоразмер: 2012 (0805); Технология монтажа: SMT; Изготовитель: АО "НПО "ЭРКОН"
footprint КИК-2012-O (Катушка индуктивности с керамическим сердечником типоразмер 2012(0805))
pins: 1, 2

## КИК-2012-27 нГн ±2% Зл
designator L?, comment 27 нГн ±2%  (value not drawn)
Катушка индуктивности с керамическим сердечником и золотым покрытием контактных площадок; Номиналиная индуктивность: 27 нГн; Добротность, не менее: 50; Резонансная частота, не менее: 2.58 ГГц; Сопротивление обмотки постоянноми току, не более: 0.25 Ом; Допустимый ток обмотки: 500 мА; Диапазон рабочих температур: от -60 до +125 ℃; Упаковка: Катушка и лента; Типоразмер: 2012 (0805); Технология монтажа: SMT; Изготовитель: АО "НПО "ЭРКОН"
footprint КИК-2012-Зл (Катушка индуктивности с керамическим сердечникомтипоразмер 2012(0805))
pins: 1, 2

## КИК-2012-27 нГн ±5% O
designator L?, comment 27 нГн ±5%  (value not drawn)
Катушка индуктивности с керамическим сердечником и  финишным покрытием контактных площадок оловом; Номиналиная индуктивность: 27 нГн; Добротность, не менее: 50; Резонансная частота, не менее: 2.58 ГГц; Сопротивление обмотки постоянноми току, не более: 0.25 Ом; Допустимый ток обмотки: 500 мА; Диапазон рабочих температур: от -60 до +125 ℃; Упаковка: Катушка и лента; Типоразмер: 2012 (0805); Технология монтажа: SMT; Изготовитель: АО "НПО "ЭРКОН"
footprint КИК-2012-O (Катушка индуктивности с керамическим сердечником типоразмер 2012(0805))
pins: 1, 2

## КИК-2012-27 нГн ±5% Зл
designator L?, comment 27 нГн ±5%  (value not drawn)
Катушка индуктивности с керамическим сердечником и золотым покрытием контактных площадок; Номиналиная индуктивность: 27 нГн; Добротность, не менее: 50; Резонансная частота, не менее: 2.58 ГГц; Сопротивление обмотки постоянноми току, не более: 0.25 Ом; Допустимый ток обмотки: 500 мА; Диапазон рабочих температур: от -60 до +125 ℃; Упаковка: Катушка и лента; Типоразмер: 2012 (0805); Технология монтажа: SMT; Изготовитель: АО "НПО "ЭРКОН"
footprint КИК-2012-Зл (Катушка индуктивности с керамическим сердечникомтипоразмер 2012(0805))
pins: 1, 2

## КИК-2012-27 нГн ±10% O
designator L?, comment 27 нГн ±10%  (value not drawn)
Катушка индуктивности с керамическим сердечником и  финишным покрытием контактных площадок оловом; Номиналиная индуктивность: 27 нГн; Добротность, не менее: 50; Резонансная частота, не менее: 2.58 ГГц; Сопротивление обмотки постоянноми току, не более: 0.25 Ом; Допустимый ток обмотки: 500 мА; Диапазон рабочих температур: от -60 до +125 ℃; Упаковка: Катушка и лента; Типоразмер: 2012 (0805); Технология монтажа: SMT; Изготовитель: АО "НПО "ЭРКОН"
footprint КИК-2012-O (Катушка индуктивности с керамическим сердечником типоразмер 2012(0805))
pins: 1, 2

## КИК-2012-27 нГн ±10% Зл
designator L?, comment 27 нГн ±10%  (value not drawn)
Катушка индуктивности с керамическим сердечником и золотым покрытием контактных площадок; Номиналиная индуктивность: 27 нГн; Добротность, не менее: 50; Резонансная частота, не менее: 2.58 ГГц; Сопротивление обмотки постоянноми току, не более: 0.25 Ом; Допустимый ток обмотки: 500 мА; Диапазон рабочих температур: от -60 до +125 ℃; Упаковка: Катушка и лента; Типоразмер: 2012 (0805); Технология монтажа: SMT; Изготовитель: АО "НПО "ЭРКОН"
footprint КИК-2012-Зл (Катушка индуктивности с керамическим сердечникомтипоразмер 2012(0805))
pins: 1, 2

## КИК-2012-33 нГн ±2% O
designator L?, comment 33 нГн ±2%  (value not drawn)
Катушка индуктивности с керамическим сердечником и  финишным покрытием контактных площадок оловом; Номиналиная индуктивность: 33 нГн; Добротность, не менее: 50; Резонансная частота, не менее: 2.15 ГГц; Сопротивление обмотки постоянноми току, не более: 0.27 Ом; Допустимый ток обмотки: 500 мА; Диапазон рабочих температур: от -60 до +125 ℃; Упаковка: Катушка и лента; Типоразмер: 2012 (0805); Технология монтажа: SMT; Изготовитель: АО "НПО "ЭРКОН"
footprint КИК-2012-O (Катушка индуктивности с керамическим сердечником типоразмер 2012(0805))
pins: 1, 2

## КИК-2012-33 нГн ±2% Зл
designator L?, comment 33 нГн ±2%  (value not drawn)
Катушка индуктивности с керамическим сердечником и золотым покрытием контактных площадок; Номиналиная индуктивность: 33 нГн; Допускаемое отклонение индуктивности: ±5%; Добротность, не менее: 50; Резонансная частота, не менее: 2.15 ГГц; Сопротивление обмотки постоянноми току, не более: 0.27 Ом; Допустимый ток обмотки: 500 мА; Диапазон рабочих температур: от -60 до +125 ℃; Упаковка: Катушка и лента; Типоразмер: 2012 (0805); Технология монтажа: SMT; Изготовитель: АО "НПО "ЭРКОН"
footprint КИК-2012-Зл (Катушка индуктивности с керамическим сердечникомтипоразмер 2012(0805))
pins: 1, 2

## КИК-2012-33 нГн ±5% O
designator L?, comment 33 нГн ±5%  (value not drawn)
Катушка индуктивности с керамическим сердечником и  финишным покрытием контактных площадок оловом; Номиналиная индуктивность: 33 нГн; Добротность, не менее: 50; Резонансная частота, не менее: 2.15 ГГц; Сопротивление обмотки постоянноми току, не более: 0.27 Ом; Допустимый ток обмотки: 500 мА; Диапазон рабочих температур: от -60 до +125 ℃; Упаковка: Катушка и лента; Типоразмер: 2012 (0805); Технология монтажа: SMT; Изготовитель: АО "НПО "ЭРКОН"
footprint КИК-2012-O (Катушка индуктивности с керамическим сердечником типоразмер 2012(0805))
pins: 1, 2

## КИК-2012-33 нГн ±5% Зл
designator L?, comment 33 нГн ±5%  (value not drawn)
Катушка индуктивности с керамическим сердечником и золотым покрытием контактных площадок; Номиналиная индуктивность: 33 нГн; Добротность, не менее: 50; Резонансная частота, не менее: 2.15 ГГц; Сопротивление обмотки постоянноми току, не более: 0.27 Ом; Допустимый ток обмотки: 500 мА; Диапазон рабочих температур: от -60 до +125 ℃; Упаковка: Катушка и лента; Типоразмер: 2012 (0805); Технология монтажа: SMT; Изготовитель: АО "НПО "ЭРКОН"
footprint КИК-2012-Зл (Катушка индуктивности с керамическим сердечникомтипоразмер 2012(0805))
pins: 1, 2

## КИК-2012-33 нГн ±10% O
designator L?, comment 33 нГн ±10%  (value not drawn)
Катушка индуктивности с керамическим сердечником и  финишным покрытием контактных площадок оловом; Номиналиная индуктивность: 33 нГн; Добротность, не менее: 50; Резонансная частота, не менее: 2.15 ГГц; Сопротивление обмотки постоянноми току, не более: 0.27 Ом; Допустимый ток обмотки: 500 мА; Диапазон рабочих температур: от -60 до +125 ℃; Упаковка: Катушка и лента; Типоразмер: 2012 (0805); Технология монтажа: SMT; Изготовитель: АО "НПО "ЭРКОН"
footprint КИК-2012-O (Катушка индуктивности с керамическим сердечником типоразмер 2012(0805))
pins: 1, 2

## КИК-2012-33 нГн ±10% Зл
designator L?, comment 33 нГн ±10%  (value not drawn)
Катушка индуктивности с керамическим сердечником и золотым покрытием контактных площадок; Номиналиная индуктивность: 33 нГн; Добротность, не менее: 50; Резонансная частота, не менее: 2.15 ГГц; Сопротивление обмотки постоянноми току, не более: 0.27 Ом; Допустимый ток обмотки: 500 мА; Диапазон рабочих температур: от -60 до +125 ℃; Упаковка: Катушка и лента; Типоразмер: 2012 (0805); Технология монтажа: SMT; Изготовитель: АО "НПО "ЭРКОН"
footprint КИК-2012-Зл (Катушка индуктивности с керамическим сердечникомтипоразмер 2012(0805))
pins: 1, 2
